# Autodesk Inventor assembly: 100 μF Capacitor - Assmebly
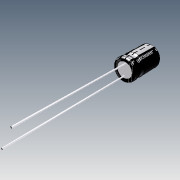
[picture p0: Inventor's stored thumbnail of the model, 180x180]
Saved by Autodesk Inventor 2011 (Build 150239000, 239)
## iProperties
Created: 2013-03
Part Number: 100 μF Capacitor - Assmebly
Document SubType Name: Assembly
Designer: Lance
Author: Lance
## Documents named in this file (4)
- C:\Inventor Projects\MPX0037 - Timer Circuit\Timer Circuit - Communica\Components\Capacitors\100 uF Capacitior\100 uF Capacitor - Assmebly.iam
- C:\Inventor Projects\MPX0037 - Timer Circuit\Timer Circuit - Communica\Components\Capacitors\100 uF Capacitior\100 uF Capacitor - Capacitor.ipt
- C:\Inventor Projects\MPX0037 - Timer Circuit\Timer Circuit - Communica\Components\Capacitors\100 uF Capacitior\100 uF Capacitor - Plastic Outer.ipt
- C:\Inventor Projects\MPX0037 - Timer Circuit\Timer Circuit - Communica\Components\Capacitors\100 uF Capacitior\100 uF Capacitor - Legs.ipt
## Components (3 placed, 3 different names)
1. 100 uF Capacitor - Capacitor:1 — Insert:1, Flush:1, Flush:2, Flush:3, Flush:4
2. 100 uF Capacitor - Plastic Outer:1 — Insert:1, Flush:1
3. 100 uF Capacitor - Legs:1 — Flush:2, Flush:3, Flush:4
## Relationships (5: Flush 4, Insert 1)
- Insert:1: 100 uF Capacitor - Capacitor:1 ↔ 100 uF Capacitor - Plastic Outer:1
- Flush:1: 100 uF Capacitor - Capacitor:1 ↔ 100 uF Capacitor - Plastic Outer:1
- Flush:2: 100 uF Capacitor - Capacitor:1 ↔ 100 uF Capacitor - Legs:1
- Flush:3: 100 uF Capacitor - Capacitor:1 ↔ 100 uF Capacitor - Legs:1
- Flush:4: 100 uF Capacitor - Capacitor:1 ↔ 100 uF Capacitor - Legs:1
